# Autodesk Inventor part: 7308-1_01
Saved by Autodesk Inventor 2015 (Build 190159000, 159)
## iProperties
Created: 2021-01
Part Number: 7308-1_01
Checked By: TraceParts S.A.
Material: Generic
Catalog Web Link: www.traceparts.com
Document SubType Name: Modeling
Designer: TraceParts
Density: 1 g/cm^3
Appearance: Default
Company: TraceParts S.A.
Author: TraceParts
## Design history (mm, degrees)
feature "7308-1_01.ipt"
body "Solid1"
